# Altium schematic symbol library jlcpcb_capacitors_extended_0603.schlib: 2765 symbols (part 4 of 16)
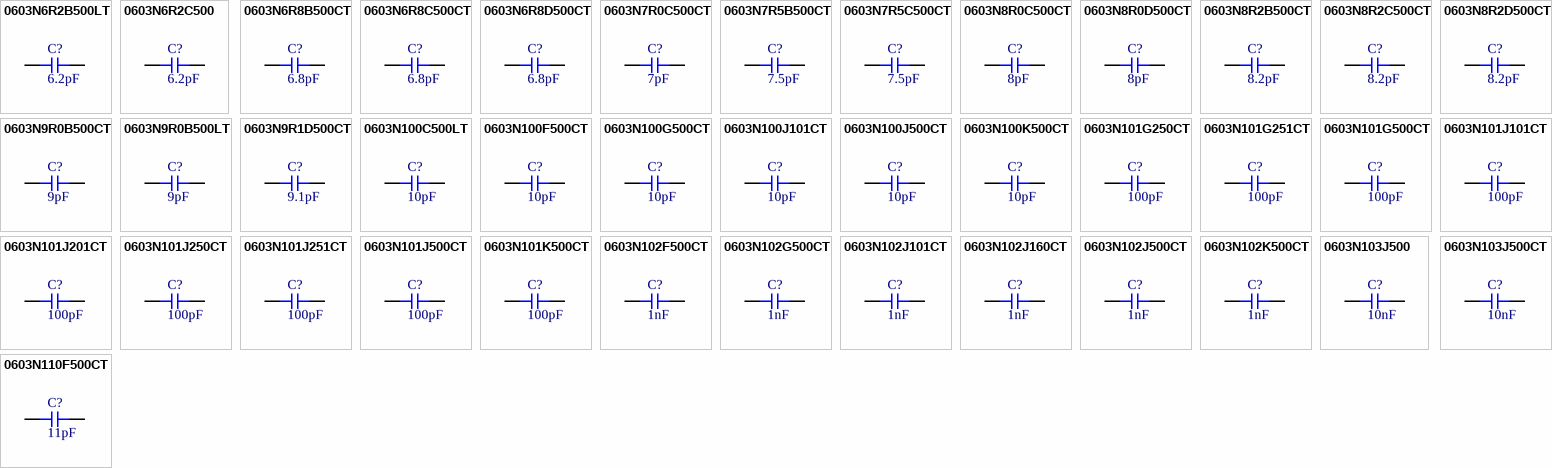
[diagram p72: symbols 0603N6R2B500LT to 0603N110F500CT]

## 0603N9R0B500CT
designator C?  Capacitance: 9pF  (hidden comment: *)
Capacitor, Ceramic (MLCC), 9pF, ±0.1pF, 50V, NP0, ±0.1pF, SMD 0603; Manufacturer: Walsin Tech Corp; Manufacturer Part Number: 0603N9R0B500CT
footprint CAP-0603 (0603 (1608M) Capacitor)
pins: 1, 2

## 0603N9R0B500LT
designator C?  Capacitance: 9pF  (hidden comment: *)
Capacitor, Ceramic (MLCC), 9pF, ±0.1pF, 50V, NP0, ±0.1pF, SMD 0603; Manufacturer: Walsin Tech Corp; Manufacturer Part Number: 0603N9R0B500LT
footprint CAP-0603 (0603 (1608M) Capacitor)
pins: 1, 2

## 0603N9R1D500CT
designator C?  Capacitance: 9.1pF  (hidden comment: *)
Capacitor, Ceramic (MLCC), 9.1pF, ±0.5pF, 50V, NP0, ±0.5pF, SMD 0603; Manufacturer: Walsin Tech Corp; Manufacturer Part Number: 0603N9R1D500CT
footprint CAP-0603 (0603 (1608M) Capacitor)
pins: 1, 2

## 0603N100C500LT
designator C?  Capacitance: 10pF  (hidden comment: *)
Capacitor, Ceramic (MLCC), 10pF, ±0.25pF, 50V, NP0, ±0.25pF, SMD 0603; Manufacturer: Walsin Tech Corp; Manufacturer Part Number: 0603N100C500LT
footprint CAP-0603 (0603 (1608M) Capacitor)
pins: 1, 2

## 0603N100F500CT
designator C?  Capacitance: 10pF  (hidden comment: *)
Capacitor, Ceramic (MLCC), 10pF, ±1%, 50V, NP0, ±1%, SMD 0603; Manufacturer: Walsin Tech Corp; Manufacturer Part Number: 0603N100F500CT
footprint CAP-0603 (0603 (1608M) Capacitor)
pins: 1, 2

## 0603N100G500CT
designator C?  Capacitance: 10pF  (hidden comment: *)
Capacitor, Ceramic (MLCC), 10pF, ±2%, 50V, NP0, ±2%, SMD 0603; Manufacturer: Walsin Tech Corp; Manufacturer Part Number: 0603N100G500CT
footprint CAP-0603 (0603 (1608M) Capacitor)
pins: 1, 2

## 0603N100J101CT
designator C?  Capacitance: 10pF  (hidden comment: *)
Capacitor, Ceramic (MLCC), 10pF, ±5%, 100V, NP0, ±5%, SMD 0603; Manufacturer: Walsin Tech Corp; Manufacturer Part Number: 0603N100J101CT
footprint CAP-0603 (0603 (1608M) Capacitor)
pins: 1, 2

## 0603N100J500CT
designator C?  Capacitance: 10pF  (hidden comment: *)
Capacitor, Ceramic (MLCC), 10pF, ±5%, 50V, NP0, ±5%, SMD 0603; Manufacturer: Walsin Tech Corp; Manufacturer Part Number: 0603N100J500CT
footprint CAP-0603 (0603 (1608M) Capacitor)
pins: 1, 2

## 0603N100K500CT
designator C?  Capacitance: 10pF  (hidden comment: *)
Capacitor, Ceramic (MLCC), 10pF, ±10%, 50V, NP0, ±10%, SMD 0603; Manufacturer: Walsin Tech Corp; Manufacturer Part Number: 0603N100K500CT
footprint CAP-0603 (0603 (1608M) Capacitor)
pins: 1, 2

## 0603N101G250CT
designator C?  Capacitance: 100pF  (hidden comment: *)
Capacitor, Ceramic (MLCC), 100pF, ±2%, 25V, NP0, ±2%, SMD 0603; Manufacturer: Walsin Tech Corp; Manufacturer Part Number: 0603N101G250CT
footprint CAP-0603 (0603 (1608M) Capacitor)
pins: 1, 2

## 0603N101G251CT
designator C?  Capacitance: 100pF  (hidden comment: *)
Capacitor, Ceramic (MLCC), 100pF, ±2%, 250V, NP0, ±2%, SMD 0603; Manufacturer: Walsin Tech Corp; Manufacturer Part Number: 0603N101G251CT
footprint CAP-0603 (0603 (1608M) Capacitor)
pins: 1, 2

## 0603N101G500CT
designator C?  Capacitance: 100pF  (hidden comment: *)
Capacitor, Ceramic (MLCC), 100pF, ±2%, 50V, NP0, ±2%, SMD 0603; Manufacturer: Walsin Tech Corp; Manufacturer Part Number: 0603N101G500CT
footprint CAP-0603 (0603 (1608M) Capacitor)
pins: 1, 2

## 0603N101J101CT
designator C?  Capacitance: 100pF  (hidden comment: *)
Capacitor, Ceramic (MLCC), 100pF, ±5%, 100V, NP0, ±5%, SMD 0603; Manufacturer: Walsin Tech Corp; Manufacturer Part Number: 0603N101J101CT
footprint CAP-0603 (0603 (1608M) Capacitor)
pins: 1, 2

## 0603N101J201CT
designator C?  Capacitance: 100pF  (hidden comment: *)
Capacitor, Ceramic (MLCC), 100pF, ±5%, 200V, NP0, ±5%, SMD 0603; Manufacturer: Walsin Tech Corp; Manufacturer Part Number: 0603N101J201CT
footprint CAP-0603 (0603 (1608M) Capacitor)
pins: 1, 2

## 0603N101J250CT
designator C?  Capacitance: 100pF  (hidden comment: *)
Capacitor, Ceramic (MLCC), 100pF, ±5%, 25V, NP0, ±5%, SMD 0603; Manufacturer: Walsin Tech Corp; Manufacturer Part Number: 0603N101J250CT
footprint CAP-0603 (0603 (1608M) Capacitor)
pins: 1, 2

## 0603N101J251CT
designator C?  Capacitance: 100pF  (hidden comment: *)
Capacitor, Ceramic (MLCC), 100pF, ±5%, 250V, NP0, ±5%, SMD 0603; Manufacturer: Walsin Tech Corp; Manufacturer Part Number: 0603N101J251CT
footprint CAP-0603 (0603 (1608M) Capacitor)
pins: 1, 2

## 0603N101J500CT
designator C?  Capacitance: 100pF  (hidden comment: *)
Capacitor, Ceramic (MLCC), 100pF, ±5%, 50V, NP0, ±5%, SMD 0603; Manufacturer: Walsin Tech Corp; Manufacturer Part Number: 0603N101J500CT
footprint CAP-0603 (0603 (1608M) Capacitor)
pins: 1, 2

## 0603N101K500CT
designator C?  Capacitance: 100pF  (hidden comment: *)
Capacitor, Ceramic (MLCC), 100pF, ±10%, 50V, NP0, ±10%, SMD 0603; Manufacturer: Walsin Tech Corp; Manufacturer Part Number: 0603N101K500CT
footprint CAP-0603 (0603 (1608M) Capacitor)
pins: 1, 2

## 0603N102F500CT
designator C?  Capacitance: 1nF  (hidden comment: *)
Capacitor, Ceramic (MLCC), 1nF, ±1%, 50V, NP0, ±1%, SMD 0603; Manufacturer: Walsin Tech Corp; Manufacturer Part Number: 0603N102F500CT
footprint CAP-0603 (0603 (1608M) Capacitor)
pins: 1, 2

## 0603N102G500CT
designator C?  Capacitance: 1nF  (hidden comment: *)
Capacitor, Ceramic (MLCC), 1nF, ±2%, 50V, NP0, ±2%, SMD 0603; Manufacturer: Walsin Tech Corp; Manufacturer Part Number: 0603N102G500CT
footprint CAP-0603 (0603 (1608M) Capacitor)
pins: 1, 2

## 0603N102J101CT
designator C?  Capacitance: 1nF  (hidden comment: *)
Capacitor, Ceramic (MLCC), 1nF, ±5%, 100V, NP0, ±5%, SMD 0603; Manufacturer: Walsin Tech Corp; Manufacturer Part Number: 0603N102J101CT
footprint CAP-0603 (0603 (1608M) Capacitor)
pins: 1, 2

## 0603N102J160CT
designator C?  Capacitance: 1nF  (hidden comment: *)
Capacitor, Ceramic (MLCC), 1nF, ±5%, 16V, NP0, ±5%, SMD 0603; Manufacturer: Walsin Tech Corp; Manufacturer Part Number: 0603N102J160CT
footprint CAP-0603 (0603 (1608M) Capacitor)
pins: 1, 2

## 0603N102J500CT
designator C?  Capacitance: 1nF  (hidden comment: *)
Capacitor, Ceramic (MLCC), 1nF, ±5%, 50V, NP0, ±5%, SMD 0603; Manufacturer: Walsin Tech Corp; Manufacturer Part Number: 0603N102J500CT
footprint CAP-0603 (0603 (1608M) Capacitor)
pins: 1, 2

## 0603N102K500CT
designator C?  Capacitance: 1nF  (hidden comment: *)
Capacitor, Ceramic (MLCC), 1nF, ±10%, 50V, NP0, ±10%, SMD 0603; Manufacturer: Walsin Tech Corp; Manufacturer Part Number: 0603N102K500CT
footprint CAP-0603 (0603 (1608M) Capacitor)
pins: 1, 2

## 0603N103J500
designator C?  Capacitance: 10nF  (hidden comment: *)
Capacitor, Ceramic (MLCC), 10nF, ±5%, 50V, NP0, ±5%, SMD 0603; Manufacturer: Walsin Tech Corp; Manufacturer Part Number: 0603N103J500
footprint CAP-0603 (0603 (1608M) Capacitor)
pins: 1, 2

## 0603N103J500CT
designator C?  Capacitance: 10nF  (hidden comment: *)
Capacitor, Ceramic (MLCC), 10nF, ±5%, 50V, NP0, ±5%, SMD 0603; Manufacturer: Walsin Tech Corp; Manufacturer Part Number: 0603N103J500CT
footprint CAP-0603 (0603 (1608M) Capacitor)
pins: 1, 2

## 0603N110F500CT
designator C?  Capacitance: 11pF  (hidden comment: *)
Capacitor, Ceramic (MLCC), 11pF, ±1%, 50V, NP0, ±1%, SMD 0603; Manufacturer: Walsin Tech Corp; Manufacturer Part Number: 0603N110F500CT
footprint CAP-0603 (0603 (1608M) Capacitor)
pins: 1, 2

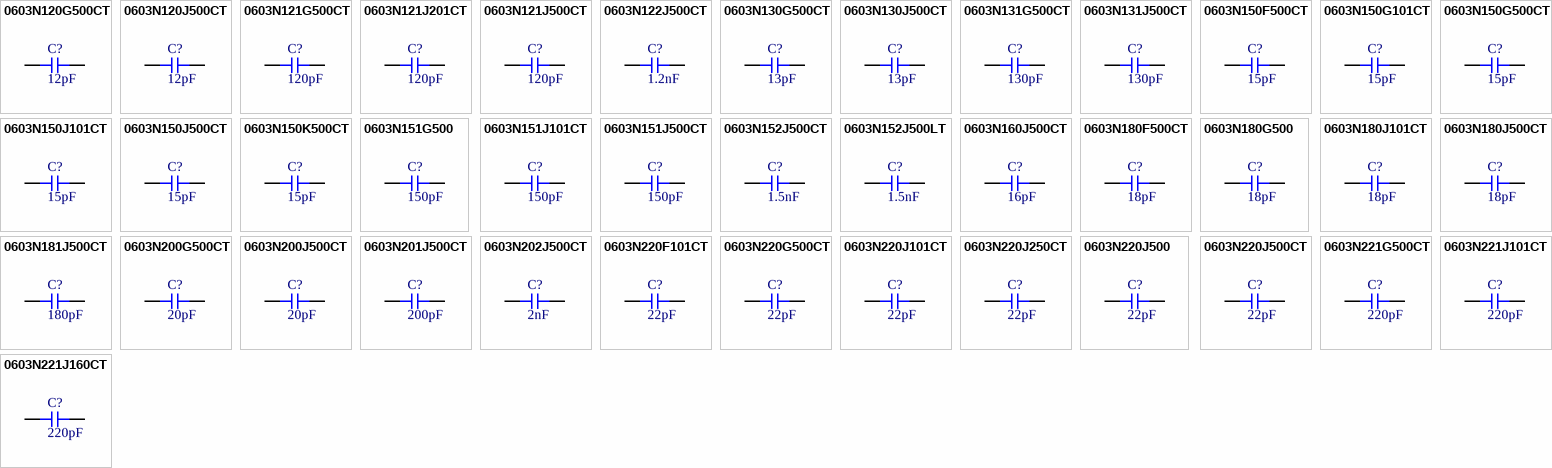
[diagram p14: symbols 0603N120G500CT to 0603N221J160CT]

## 0603N120G500CT
designator C?  Capacitance: 12pF  (hidden comment: *)
Capacitor, Ceramic (MLCC), 12pF, ±2%, 50V, NP0, ±2%, SMD 0603; Manufacturer: Walsin Tech Corp; Manufacturer Part Number: 0603N120G500CT
footprint CAP-0603 (0603 (1608M) Capacitor)
pins: 1, 2

## 0603N120J500CT
designator C?  Capacitance: 12pF  (hidden comment: *)
Capacitor, Ceramic (MLCC), 12pF, ±5%, 50V, NP0, ±5%, SMD 0603; Manufacturer: Walsin Tech Corp; Manufacturer Part Number: 0603N120J500CT
footprint CAP-0603 (0603 (1608M) Capacitor)
pins: 1, 2

## 0603N121G500CT
designator C?  Capacitance: 120pF  (hidden comment: *)
Capacitor, Ceramic (MLCC), 120pF, ±2%, 50V, NP0, ±2%, SMD 0603; Manufacturer: Walsin Tech Corp; Manufacturer Part Number: 0603N121G500CT
footprint CAP-0603 (0603 (1608M) Capacitor)
pins: 1, 2

## 0603N121J201CT
designator C?  Capacitance: 120pF  (hidden comment: *)
Capacitor, Ceramic (MLCC), 120pF, ±5%, 200V, NP0, ±5%, SMD 0603; Manufacturer: Walsin Tech Corp; Manufacturer Part Number: 0603N121J201CT
footprint CAP-0603 (0603 (1608M) Capacitor)
pins: 1, 2

## 0603N121J500CT
designator C?  Capacitance: 120pF  (hidden comment: *)
Capacitor, Ceramic (MLCC), 120pF, ±5%, 50V, NP0, ±5%, SMD 0603; Manufacturer: Walsin Tech Corp; Manufacturer Part Number: 0603N121J500CT
footprint CAP-0603 (0603 (1608M) Capacitor)
pins: 1, 2

## 0603N122J500CT
designator C?  Capacitance: 1.2nF  (hidden comment: *)
Capacitor, Ceramic (MLCC), 1.2nF, ±5%, 50V, NP0, ±5%, SMD 0603; Manufacturer: Walsin Tech Corp; Manufacturer Part Number: 0603N122J500CT
footprint CAP-0603 (0603 (1608M) Capacitor)
pins: 1, 2

## 0603N130G500CT
designator C?  Capacitance: 13pF  (hidden comment: *)
Capacitor, Ceramic (MLCC), 13pF, ±2%, 50V, NP0, ±2%, SMD 0603; Manufacturer: Walsin Tech Corp; Manufacturer Part Number: 0603N130G500CT
footprint CAP-0603 (0603 (1608M) Capacitor)
pins: 1, 2

## 0603N130J500CT
designator C?  Capacitance: 13pF  (hidden comment: *)
Capacitor, Ceramic (MLCC), 13pF, ±5%, 50V, NP0, ±5%, SMD 0603; Manufacturer: Walsin Tech Corp; Manufacturer Part Number: 0603N130J500CT
footprint CAP-0603 (0603 (1608M) Capacitor)
pins: 1, 2

## 0603N131G500CT
designator C?  Capacitance: 130pF  (hidden comment: *)
Capacitor, Ceramic (MLCC), 130pF, ±2%, 50V, NP0, ±2%, SMD 0603; Manufacturer: Walsin Tech Corp; Manufacturer Part Number: 0603N131G500CT
footprint CAP-0603 (0603 (1608M) Capacitor)
pins: 1, 2

## 0603N131J500CT
designator C?  Capacitance: 130pF  (hidden comment: *)
Capacitor, Ceramic (MLCC), 130pF, ±5%, 50V, NP0, ±5%, SMD 0603; Manufacturer: Walsin Tech Corp; Manufacturer Part Number: 0603N131J500CT
footprint CAP-0603 (0603 (1608M) Capacitor)
pins: 1, 2

## 0603N150F500CT
designator C?  Capacitance: 15pF  (hidden comment: *)
Capacitor, Ceramic (MLCC), 15pF, ±1%, 50V, NP0, ±1%, SMD 0603; Manufacturer: Walsin Tech Corp; Manufacturer Part Number: 0603N150F500CT
footprint CAP-0603 (0603 (1608M) Capacitor)
pins: 1, 2

## 0603N150G101CT
designator C?  Capacitance: 15pF  (hidden comment: *)
Capacitor, Ceramic (MLCC), 15pF, ±2%, 100V, NP0, ±2%, SMD 0603; Manufacturer: Walsin Tech Corp; Manufacturer Part Number: 0603N150G101CT
footprint CAP-0603 (0603 (1608M) Capacitor)
pins: 1, 2

## 0603N150G500CT
designator C?  Capacitance: 15pF  (hidden comment: *)
Capacitor, Ceramic (MLCC), 15pF, ±2%, 50V, NP0, ±2%, SMD 0603; Manufacturer: Walsin Tech Corp; Manufacturer Part Number: 0603N150G500CT
footprint CAP-0603 (0603 (1608M) Capacitor)
pins: 1, 2

## 0603N150J101CT
designator C?  Capacitance: 15pF  (hidden comment: *)
Capacitor, Ceramic (MLCC), 15pF, ±5%, 100V, NP0, ±5%, SMD 0603; Manufacturer: Walsin Tech Corp; Manufacturer Part Number: 0603N150J101CT
footprint CAP-0603 (0603 (1608M) Capacitor)
pins: 1, 2

## 0603N150J500CT
designator C?  Capacitance: 15pF  (hidden comment: *)
Capacitor, Ceramic (MLCC), 15pF, ±5%, 50V, NP0, ±5%, SMD 0603; Manufacturer: Walsin Tech Corp; Manufacturer Part Number: 0603N150J500CT
footprint CAP-0603 (0603 (1608M) Capacitor)
pins: 1, 2

## 0603N150K500CT
designator C?  Capacitance: 15pF  (hidden comment: *)
Capacitor, Ceramic (MLCC), 15pF, ±10%, 50V, NP0, ±10%, SMD 0603; Manufacturer: Walsin Tech Corp; Manufacturer Part Number: 0603N150K500CT
footprint CAP-0603 (0603 (1608M) Capacitor)
pins: 1, 2

## 0603N151G500
designator C?  Capacitance: 150pF  (hidden comment: *)
Capacitor, Ceramic (MLCC), 150pF, ±2%, 50V, NP0, ±2%, SMD 0603; Manufacturer: Walsin Tech Corp; Manufacturer Part Number: 0603N151G500
footprint CAP-0603 (0603 (1608M) Capacitor)
pins: 1, 2

## 0603N151J101CT
designator C?  Capacitance: 150pF  (hidden comment: *)
Capacitor, Ceramic (MLCC), 150pF, ±5%, 100V, NP0, ±5%, SMD 0603; Manufacturer: Walsin Tech Corp; Manufacturer Part Number: 0603N151J101CT
footprint CAP-0603 (0603 (1608M) Capacitor)
pins: 1, 2

## 0603N151J500CT
designator C?  Capacitance: 150pF  (hidden comment: *)
Capacitor, Ceramic (MLCC), 150pF, ±5%, 50V, NP0, ±5%, SMD 0603; Manufacturer: Walsin Tech Corp; Manufacturer Part Number: 0603N151J500CT
footprint CAP-0603 (0603 (1608M) Capacitor)
pins: 1, 2

## 0603N152J500CT
designator C?  Capacitance: 1.5nF  (hidden comment: *)
Capacitor, Ceramic (MLCC), 1.5nF, ±5%, 50V, NP0, ±5%, SMD 0603; Manufacturer: Walsin Tech Corp; Manufacturer Part Number: 0603N152J500CT
footprint CAP-0603 (0603 (1608M) Capacitor)
pins: 1, 2

## 0603N152J500LT
designator C?  Capacitance: 1.5nF  (hidden comment: *)
Capacitor, Ceramic (MLCC), 1.5nF, ±5%, 50V, NP0, ±5%, SMD 0603; Manufacturer: Walsin Tech Corp; Manufacturer Part Number: 0603N152J500LT
footprint CAP-0603 (0603 (1608M) Capacitor)
pins: 1, 2

## 0603N160J500CT
designator C?  Capacitance: 16pF  (hidden comment: *)
Capacitor, Ceramic (MLCC), 16pF, ±5%, 50V, NP0, ±5%, SMD 0603; Manufacturer: Walsin Tech Corp; Manufacturer Part Number: 0603N160J500CT
footprint CAP-0603 (0603 (1608M) Capacitor)
pins: 1, 2

## 0603N180F500CT
designator C?  Capacitance: 18pF  (hidden comment: *)
Capacitor, Ceramic (MLCC), 18pF, ±1%, 50V, NP0, ±1%, SMD 0603; Manufacturer: Walsin Tech Corp; Manufacturer Part Number: 0603N180F500CT
footprint CAP-0603 (0603 (1608M) Capacitor)
pins: 1, 2

## 0603N180G500
designator C?  Capacitance: 18pF  (hidden comment: *)
Capacitor, Ceramic (MLCC), 18pF, ±2%, 50V, NP0, ±2%, SMD 0603; Manufacturer: Walsin Tech Corp; Manufacturer Part Number: 0603N180G500
footprint CAP-0603 (0603 (1608M) Capacitor)
pins: 1, 2

## 0603N180J101CT
designator C?  Capacitance: 18pF  (hidden comment: *)
Capacitor, Ceramic (MLCC), 18pF, ±5%, 100V, NP0, ±5%, SMD 0603; Manufacturer: Walsin Tech Corp; Manufacturer Part Number: 0603N180J101CT
footprint CAP-0603 (0603 (1608M) Capacitor)
pins: 1, 2

## 0603N180J500CT
designator C?  Capacitance: 18pF  (hidden comment: *)
Capacitor, Ceramic (MLCC), 18pF, ±5%, 50V, NP0, ±5%, SMD 0603; Manufacturer: Walsin Tech Corp; Manufacturer Part Number: 0603N180J500CT
footprint CAP-0603 (0603 (1608M) Capacitor)
pins: 1, 2

## 0603N181J500CT
designator C?  Capacitance: 180pF  (hidden comment: *)
Capacitor, Ceramic (MLCC), 180pF, ±5%, 50V, NP0, ±5%, SMD 0603; Manufacturer: Walsin Tech Corp; Manufacturer Part Number: 0603N181J500CT
footprint CAP-0603 (0603 (1608M) Capacitor)
pins: 1, 2

## 0603N200G500CT
designator C?  Capacitance: 20pF  (hidden comment: *)
Capacitor, Ceramic (MLCC), 20pF, ±2%, 50V, NP0, ±2%, SMD 0603; Manufacturer: Walsin Tech Corp; Manufacturer Part Number: 0603N200G500CT
footprint CAP-0603 (0603 (1608M) Capacitor)
pins: 1, 2

## 0603N200J500CT
designator C?  Capacitance: 20pF  (hidden comment: *)
Capacitor, Ceramic (MLCC), 20pF, ±5%, 50V, NP0, ±5%, SMD 0603; Manufacturer: Walsin Tech Corp; Manufacturer Part Number: 0603N200J500CT
footprint CAP-0603 (0603 (1608M) Capacitor)
pins: 1, 2

## 0603N201J500CT
designator C?  Capacitance: 200pF  (hidden comment: *)
Capacitor, Ceramic (MLCC), 200pF, ±5%, 50V, NP0, ±5%, SMD 0603; Manufacturer: Walsin Tech Corp; Manufacturer Part Number: 0603N201J500CT
footprint CAP-0603 (0603 (1608M) Capacitor)
pins: 1, 2

## 0603N202J500CT
designator C?  Capacitance: 2nF  (hidden comment: *)
Capacitor, Ceramic (MLCC), 2nF, ±5%, 50V, NP0, ±5%, SMD 0603; Manufacturer: Walsin Tech Corp; Manufacturer Part Number: 0603N202J500CT
footprint CAP-0603 (0603 (1608M) Capacitor)
pins: 1, 2

## 0603N220F101CT
designator C?  Capacitance: 22pF  (hidden comment: *)
Capacitor, Ceramic (MLCC), 22pF, ±1%, 100V, NP0, ±1%, SMD 0603; Manufacturer: Walsin Tech Corp; Manufacturer Part Number: 0603N220F101CT
footprint CAP-0603 (0603 (1608M) Capacitor)
pins: 1, 2

## 0603N220G500CT
designator C?  Capacitance: 22pF  (hidden comment: *)
Capacitor, Ceramic (MLCC), 22pF, ±2%, 50V, NP0, ±2%, SMD 0603; Manufacturer: Walsin Tech Corp; Manufacturer Part Number: 0603N220G500CT
footprint CAP-0603 (0603 (1608M) Capacitor)
pins: 1, 2

## 0603N220J101CT
designator C?  Capacitance: 22pF  (hidden comment: *)
Capacitor, Ceramic (MLCC), 22pF, ±5%, 100V, NP0, ±5%, SMD 0603; Manufacturer: Walsin Tech Corp; Manufacturer Part Number: 0603N220J101CT
footprint CAP-0603 (0603 (1608M) Capacitor)
pins: 1, 2

## 0603N220J250CT
designator C?  Capacitance: 22pF  (hidden comment: *)
Capacitor, Ceramic (MLCC), 22pF, ±5%, 25V, NP0, ±5%, SMD 0603; Manufacturer: Walsin Tech Corp; Manufacturer Part Number: 0603N220J250CT
footprint CAP-0603 (0603 (1608M) Capacitor)
pins: 1, 2

## 0603N220J500
designator C?  Capacitance: 22pF  (hidden comment: *)
Capacitor, Ceramic (MLCC), 22pF, ±5%, 50V, NP0, ±5%, SMD 0603; Manufacturer: Walsin Tech Corp; Manufacturer Part Number: 0603N220J500
footprint CAP-0603 (0603 (1608M) Capacitor)
pins: 1, 2

## 0603N220J500CT
designator C?  Capacitance: 22pF  (hidden comment: *)
Capacitor, Ceramic (MLCC), 22pF, ±5%, 50V, NP0, ±5%, SMD 0603; Manufacturer: Walsin Tech Corp; Manufacturer Part Number: 0603N220J500CT
footprint CAP-0603 (0603 (1608M) Capacitor)
pins: 1, 2

## 0603N221G500CT
designator C?  Capacitance: 220pF  (hidden comment: *)
Capacitor, Ceramic (MLCC), 220pF, ±2%, 50V, NP0, ±2%, SMD 0603; Manufacturer: Walsin Tech Corp; Manufacturer Part Number: 0603N221G500CT
footprint CAP-0603 (0603 (1608M) Capacitor)
pins: 1, 2

## 0603N221J101CT
designator C?  Capacitance: 220pF  (hidden comment: *)
Capacitor, Ceramic (MLCC), 220pF, ±5%, 100V, NP0, ±5%, SMD 0603; Manufacturer: Walsin Tech Corp; Manufacturer Part Number: 0603N221J101CT
footprint CAP-0603 (0603 (1608M) Capacitor)
pins: 1, 2

## 0603N221J160CT
designator C?  Capacitance: 220pF  (hidden comment: *)
Capacitor, Ceramic (MLCC), 220pF, ±5%, 16V, NP0, ±5%, SMD 0603; Manufacturer: Walsin Tech Corp; Manufacturer Part Number: 0603N221J160CT
footprint CAP-0603 (0603 (1608M) Capacitor)
pins: 1, 2

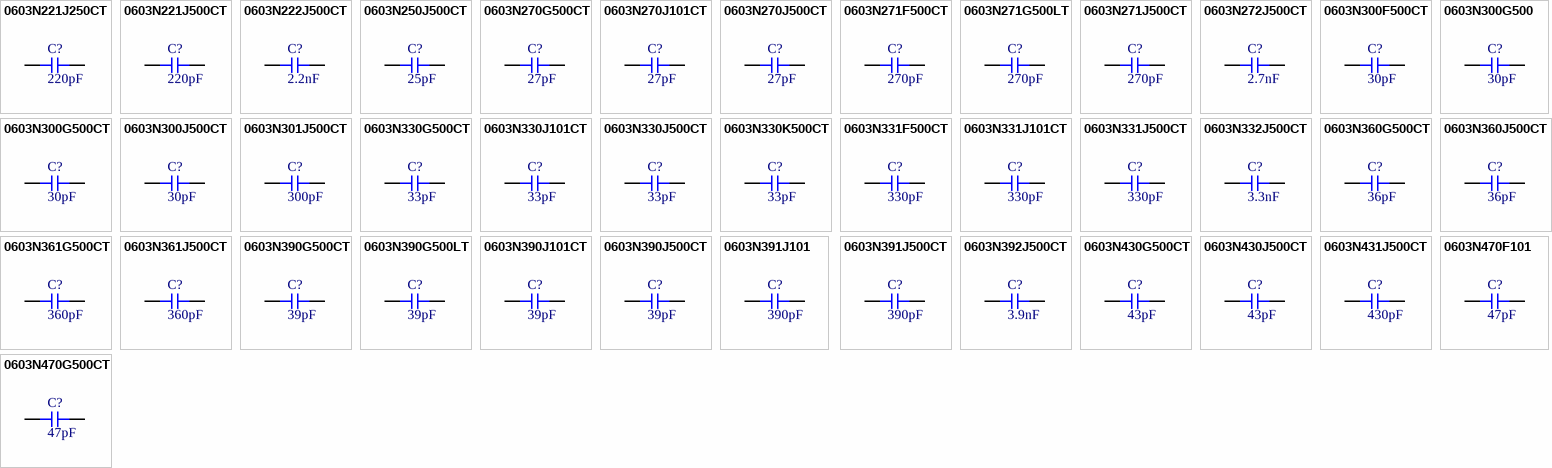
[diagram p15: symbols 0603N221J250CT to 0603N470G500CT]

## 0603N221J250CT
designator C?  Capacitance: 220pF  (hidden comment: *)
Capacitor, Ceramic (MLCC), 220pF, ±5%, 25V, NP0, ±5%, SMD 0603; Manufacturer: Walsin Tech Corp; Manufacturer Part Number: 0603N221J250CT
footprint CAP-0603 (0603 (1608M) Capacitor)
pins: 1, 2

## 0603N221J500CT
designator C?  Capacitance: 220pF  (hidden comment: *)
Capacitor, Ceramic (MLCC), 220pF, ±5%, 50V, NP0, ±5%, SMD 0603; Manufacturer: Walsin Tech Corp; Manufacturer Part Number: 0603N221J500CT
footprint CAP-0603 (0603 (1608M) Capacitor)
pins: 1, 2

## 0603N222J500CT
designator C?  Capacitance: 2.2nF  (hidden comment: *)
Capacitor, Ceramic (MLCC), 2.2nF, ±5%, 50V, NP0, ±5%, SMD 0603; Manufacturer: Walsin Tech Corp; Manufacturer Part Number: 0603N222J500CT
footprint CAP-0603 (0603 (1608M) Capacitor)
pins: 1, 2

## 0603N250J500CT
designator C?  Capacitance: 25pF  (hidden comment: *)
Capacitor, Ceramic (MLCC), 25pF, ±5%, 50V, NP0, ±5%, SMD 0603; Manufacturer: Walsin Tech Corp; Manufacturer Part Number: 0603N250J500CT
footprint CAP-0603 (0603 (1608M) Capacitor)
pins: 1, 2

## 0603N270G500CT
designator C?  Capacitance: 27pF  (hidden comment: *)
Capacitor, Ceramic (MLCC), 27pF, ±2%, 50V, NP0, ±2%, SMD 0603; Manufacturer: Walsin Tech Corp; Manufacturer Part Number: 0603N270G500CT
footprint CAP-0603 (0603 (1608M) Capacitor)
pins: 1, 2

## 0603N270J101CT
designator C?  Capacitance: 27pF  (hidden comment: *)
Capacitor, Ceramic (MLCC), 27pF, ±5%, 100V, NP0, ±5%, SMD 0603; Manufacturer: Walsin Tech Corp; Manufacturer Part Number: 0603N270J101CT
footprint CAP-0603 (0603 (1608M) Capacitor)
pins: 1, 2

## 0603N270J500CT
designator C?  Capacitance: 27pF  (hidden comment: *)
Capacitor, Ceramic (MLCC), 27pF, ±5%, 50V, NP0, ±5%, SMD 0603; Manufacturer: Walsin Tech Corp; Manufacturer Part Number: 0603N270J500CT
footprint CAP-0603 (0603 (1608M) Capacitor)
pins: 1, 2

## 0603N271F500CT
designator C?  Capacitance: 270pF  (hidden comment: *)
Capacitor, Ceramic (MLCC), 270pF, ±1%, 50V, NP0, ±1%, SMD 0603; Manufacturer: Walsin Tech Corp; Manufacturer Part Number: 0603N271F500CT
footprint CAP-0603 (0603 (1608M) Capacitor)
pins: 1, 2

## 0603N271G500LT
designator C?  Capacitance: 270pF  (hidden comment: *)
Capacitor, Ceramic (MLCC), 270pF, ±2%, 50V, NP0, ±2%, SMD 0603; Manufacturer: Walsin Tech Corp; Manufacturer Part Number: 0603N271G500LT
footprint CAP-0603 (0603 (1608M) Capacitor)
pins: 1, 2

## 0603N271J500CT
designator C?  Capacitance: 270pF  (hidden comment: *)
Capacitor, Ceramic (MLCC), 270pF, ±5%, 50V, NP0, ±5%, SMD 0603; Manufacturer: Walsin Tech Corp; Manufacturer Part Number: 0603N271J500CT
footprint CAP-0603 (0603 (1608M) Capacitor)
pins: 1, 2

## 0603N272J500CT
designator C?  Capacitance: 2.7nF  (hidden comment: *)
Capacitor, Ceramic (MLCC), 2.7nF, ±5%, 50V, NP0, ±5%, SMD 0603; Manufacturer: Walsin Tech Corp; Manufacturer Part Number: 0603N272J500CT
footprint CAP-0603 (0603 (1608M) Capacitor)
pins: 1, 2

## 0603N300F500CT
designator C?  Capacitance: 30pF  (hidden comment: *)
Capacitor, Ceramic (MLCC), 30pF, ±1%, 50V, NP0, ±1%, SMD 0603; Manufacturer: Walsin Tech Corp; Manufacturer Part Number: 0603N300F500CT
footprint CAP-0603 (0603 (1608M) Capacitor)
pins: 1, 2

## 0603N300G500
designator C?  Capacitance: 30pF  (hidden comment: *)
Capacitor, Ceramic (MLCC), 30pF, ±2%, 50V, NP0, ±2%, SMD 0603; Manufacturer: Walsin Tech Corp; Manufacturer Part Number: 0603N300G500
footprint CAP-0603 (0603 (1608M) Capacitor)
pins: 1, 2

## 0603N300G500CT
designator C?  Capacitance: 30pF  (hidden comment: *)
Capacitor, Ceramic (MLCC), 30pF, ±2%, 50V, NP0, ±2%, SMD 0603; Manufacturer: Walsin Tech Corp; Manufacturer Part Number: 0603N300G500CT
footprint CAP-0603 (0603 (1608M) Capacitor)
pins: 1, 2

## 0603N300J500CT
designator C?  Capacitance: 30pF  (hidden comment: *)
Capacitor, Ceramic (MLCC), 30pF, ±5%, 50V, NP0, ±5%, SMD 0603; Manufacturer: Walsin Tech Corp; Manufacturer Part Number: 0603N300J500CT
footprint CAP-0603 (0603 (1608M) Capacitor)
pins: 1, 2

## 0603N301J500CT
designator C?  Capacitance: 300pF  (hidden comment: *)
Capacitor, Ceramic (MLCC), 300pF, ±5%, 50V, NP0, ±5%, SMD 0603; Manufacturer: Walsin Tech Corp; Manufacturer Part Number: 0603N301J500CT
footprint CAP-0603 (0603 (1608M) Capacitor)
pins: 1, 2

## 0603N330G500CT
designator C?  Capacitance: 33pF  (hidden comment: *)
Capacitor, Ceramic (MLCC), 33pF, ±2%, 50V, NP0, ±2%, SMD 0603; Manufacturer: Walsin Tech Corp; Manufacturer Part Number: 0603N330G500CT
footprint CAP-0603 (0603 (1608M) Capacitor)
pins: 1, 2

## 0603N330J101CT
designator C?  Capacitance: 33pF  (hidden comment: *)
Capacitor, Ceramic (MLCC), 33pF, ±5%, 100V, NP0, ±5%, SMD 0603; Manufacturer: Walsin Tech Corp; Manufacturer Part Number: 0603N330J101CT
footprint CAP-0603 (0603 (1608M) Capacitor)
pins: 1, 2

## 0603N330J500CT
designator C?  Capacitance: 33pF  (hidden comment: *)
Capacitor, Ceramic (MLCC), 33pF, ±5%, 50V, NP0, ±5%, SMD 0603; Manufacturer: Walsin Tech Corp; Manufacturer Part Number: 0603N330J500CT
footprint CAP-0603 (0603 (1608M) Capacitor)
pins: 1, 2

## 0603N330K500CT
designator C?  Capacitance: 33pF  (hidden comment: *)
Capacitor, Ceramic (MLCC), 33pF, ±10%, 50V, NP0, ±10%, SMD 0603; Manufacturer: Walsin Tech Corp; Manufacturer Part Number: 0603N330K500CT
footprint CAP-0603 (0603 (1608M) Capacitor)
pins: 1, 2

## 0603N331F500CT
designator C?  Capacitance: 330pF  (hidden comment: *)
Capacitor, Ceramic (MLCC), 330pF, ±1%, 50V, NP0, ±1%, SMD 0603; Manufacturer: Walsin Tech Corp; Manufacturer Part Number: 0603N331F500CT
footprint CAP-0603 (0603 (1608M) Capacitor)
pins: 1, 2

## 0603N331J101CT
designator C?  Capacitance: 330pF  (hidden comment: *)
Capacitor, Ceramic (MLCC), 330pF, ±5%, 100V, NP0, ±5%, SMD 0603; Manufacturer: Walsin Tech Corp; Manufacturer Part Number: 0603N331J101CT
footprint CAP-0603 (0603 (1608M) Capacitor)
pins: 1, 2

## 0603N331J500CT
designator C?  Capacitance: 330pF  (hidden comment: *)
Capacitor, Ceramic (MLCC), 330pF, ±5%, 50V, NP0, ±5%, SMD 0603; Manufacturer: Walsin Tech Corp; Manufacturer Part Number: 0603N331J500CT
footprint CAP-0603 (0603 (1608M) Capacitor)
pins: 1, 2

## 0603N332J500CT
designator C?  Capacitance: 3.3nF  (hidden comment: *)
Capacitor, Ceramic (MLCC), 3.3nF, ±5%, 50V, NP0, ±5%, SMD 0603; Manufacturer: Walsin Tech Corp; Manufacturer Part Number: 0603N332J500CT
footprint CAP-0603 (0603 (1608M) Capacitor)
pins: 1, 2

## 0603N360G500CT
designator C?  Capacitance: 36pF  (hidden comment: *)
Capacitor, Ceramic (MLCC), 36pF, ±2%, 50V, NP0, ±2%, SMD 0603; Manufacturer: Walsin Tech Corp; Manufacturer Part Number: 0603N360G500CT
footprint CAP-0603 (0603 (1608M) Capacitor)
pins: 1, 2

## 0603N360J500CT
designator C?  Capacitance: 36pF  (hidden comment: *)
Capacitor, Ceramic (MLCC), 36pF, ±5%, 50V, NP0, ±5%, SMD 0603; Manufacturer: Walsin Tech Corp; Manufacturer Part Number: 0603N360J500CT
footprint CAP-0603 (0603 (1608M) Capacitor)
pins: 1, 2

## 0603N361G500CT
designator C?  Capacitance: 360pF  (hidden comment: *)
Capacitor, Ceramic (MLCC), 360pF, ±2%, 50V, NP0, ±2%, SMD 0603; Manufacturer: Walsin Tech Corp; Manufacturer Part Number: 0603N361G500CT
footprint CAP-0603 (0603 (1608M) Capacitor)
pins: 1, 2

## 0603N361J500CT
designator C?  Capacitance: 360pF  (hidden comment: *)
Capacitor, Ceramic (MLCC), 360pF, ±5%, 50V, NP0, ±5%, SMD 0603; Manufacturer: Walsin Tech Corp; Manufacturer Part Number: 0603N361J500CT
footprint CAP-0603 (0603 (1608M) Capacitor)
pins: 1, 2

## 0603N390G500CT
designator C?  Capacitance: 39pF  (hidden comment: *)
Capacitor, Ceramic (MLCC), 39pF, ±2%, 50V, NP0, ±2%, SMD 0603; Manufacturer: Walsin Tech Corp; Manufacturer Part Number: 0603N390G500CT
footprint CAP-0603 (0603 (1608M) Capacitor)
pins: 1, 2

## 0603N390G500LT
designator C?  Capacitance: 39pF  (hidden comment: *)
Capacitor, Ceramic (MLCC), 39pF, ±2%, 50V, NP0, ±2%, SMD 0603; Manufacturer: Walsin Tech Corp; Manufacturer Part Number: 0603N390G500LT
footprint CAP-0603 (0603 (1608M) Capacitor)
pins: 1, 2

## 0603N390J101CT
designator C?  Capacitance: 39pF  (hidden comment: *)
Capacitor, Ceramic (MLCC), 39pF, ±5%, 100V, NP0, ±5%, SMD 0603; Manufacturer: Walsin Tech Corp; Manufacturer Part Number: 0603N390J101CT
footprint CAP-0603 (0603 (1608M) Capacitor)
pins: 1, 2

## 0603N390J500CT
designator C?  Capacitance: 39pF  (hidden comment: *)
Capacitor, Ceramic (MLCC), 39pF, ±5%, 50V, NP0, ±5%, SMD 0603; Manufacturer: Walsin Tech Corp; Manufacturer Part Number: 0603N390J500CT
footprint CAP-0603 (0603 (1608M) Capacitor)
pins: 1, 2

## 0603N391J101
designator C?  Capacitance: 390pF  (hidden comment: *)
Capacitor, Ceramic (MLCC), 390pF, ±5%, 100V, NP0, ±5%, SMD 0603; Manufacturer: Walsin Tech Corp; Manufacturer Part Number: 0603N391J101
footprint CAP-0603 (0603 (1608M) Capacitor)
pins: 1, 2

## 0603N391J500CT
designator C?  Capacitance: 390pF  (hidden comment: *)
Capacitor, Ceramic (MLCC), 390pF, ±5%, 50V, NP0, ±5%, SMD 0603; Manufacturer: Walsin Tech Corp; Manufacturer Part Number: 0603N391J500CT
footprint CAP-0603 (0603 (1608M) Capacitor)
pins: 1, 2

## 0603N392J500CT
designator C?  Capacitance: 3.9nF  (hidden comment: *)
Capacitor, Ceramic (MLCC), 3.9nF, ±5%, 50V, NP0, ±5%, SMD 0603; Manufacturer: Walsin Tech Corp; Manufacturer Part Number: 0603N392J500CT
footprint CAP-0603 (0603 (1608M) Capacitor)
pins: 1, 2

## 0603N430G500CT
designator C?  Capacitance: 43pF  (hidden comment: *)
Capacitor, Ceramic (MLCC), 43pF, ±2%, 50V, NP0, ±2%, SMD 0603; Manufacturer: Walsin Tech Corp; Manufacturer Part Number: 0603N430G500CT
footprint CAP-0603 (0603 (1608M) Capacitor)
pins: 1, 2

## 0603N430J500CT
designator C?  Capacitance: 43pF  (hidden comment: *)
Capacitor, Ceramic (MLCC), 43pF, ±5%, 50V, NP0, ±5%, SMD 0603; Manufacturer: Walsin Tech Corp; Manufacturer Part Number: 0603N430J500CT
footprint CAP-0603 (0603 (1608M) Capacitor)
pins: 1, 2

## 0603N431J500CT
designator C?  Capacitance: 430pF  (hidden comment: *)
Capacitor, Ceramic (MLCC), 430pF, ±5%, 50V, NP0, ±5%, SMD 0603; Manufacturer: Walsin Tech Corp; Manufacturer Part Number: 0603N431J500CT
footprint CAP-0603 (0603 (1608M) Capacitor)
pins: 1, 2

## 0603N470F101
designator C?  Capacitance: 47pF  (hidden comment: *)
Capacitor, Ceramic (MLCC), 47pF, ±1%, 100V, NP0, ±1%, SMD 0603; Manufacturer: Walsin Tech Corp; Manufacturer Part Number: 0603N470F101
footprint CAP-0603 (0603 (1608M) Capacitor)
pins: 1, 2

## 0603N470G500CT
designator C?  Capacitance: 47pF  (hidden comment: *)
Capacitor, Ceramic (MLCC), 47pF, ±2%, 50V, NP0, ±2%, SMD 0603; Manufacturer: Walsin Tech Corp; Manufacturer Part Number: 0603N470G500CT
footprint CAP-0603 (0603 (1608M) Capacitor)
pins: 1, 2

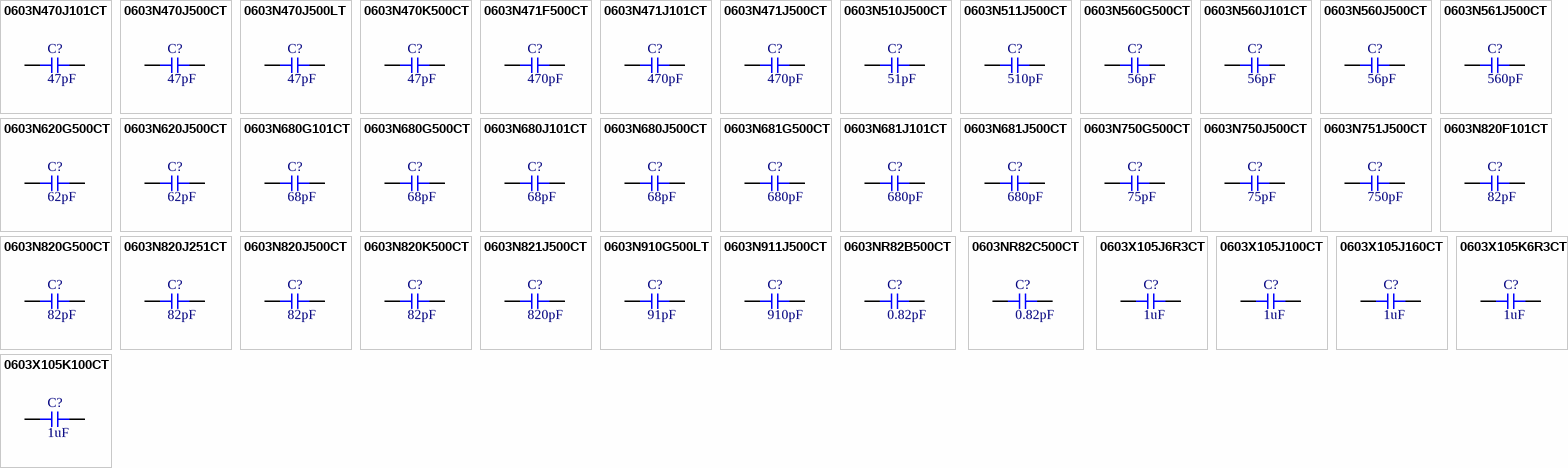
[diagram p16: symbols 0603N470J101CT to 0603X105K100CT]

## 0603N470J101CT
designator C?  Capacitance: 47pF  (hidden comment: *)
Capacitor, Ceramic (MLCC), 47pF, ±5%, 100V, NP0, ±5%, SMD 0603; Manufacturer: Walsin Tech Corp; Manufacturer Part Number: 0603N470J101CT
footprint CAP-0603 (0603 (1608M) Capacitor)
pins: 1, 2

## 0603N470J500CT
designator C?  Capacitance: 47pF  (hidden comment: *)
Capacitor, Ceramic (MLCC), 47pF, ±5%, 50V, NP0, ±5%, SMD 0603; Manufacturer: Walsin Tech Corp; Manufacturer Part Number: 0603N470J500CT
footprint CAP-0603 (0603 (1608M) Capacitor)
pins: 1, 2

## 0603N470J500LT
designator C?  Capacitance: 47pF  (hidden comment: *)
Capacitor, Ceramic (MLCC), 47pF, ±5%, 50V, NP0, ±5%, SMD 0603; Manufacturer: Walsin Tech Corp; Manufacturer Part Number: 0603N470J500LT
footprint CAP-0603 (0603 (1608M) Capacitor)
pins: 1, 2

## 0603N470K500CT
designator C?  Capacitance: 47pF  (hidden comment: *)
Capacitor, Ceramic (MLCC), 47pF, ±10%, 50V, NP0, ±10%, SMD 0603; Manufacturer: Walsin Tech Corp; Manufacturer Part Number: 0603N470K500CT
footprint CAP-0603 (0603 (1608M) Capacitor)
pins: 1, 2

## 0603N471F500CT
designator C?  Capacitance: 470pF  (hidden comment: *)
Capacitor, Ceramic (MLCC), 470pF, ±1%, 50V, NP0, ±1%, SMD 0603; Manufacturer: Walsin Tech Corp; Manufacturer Part Number: 0603N471F500CT
footprint CAP-0603 (0603 (1608M) Capacitor)
pins: 1, 2

## 0603N471J101CT
designator C?  Capacitance: 470pF  (hidden comment: *)
Capacitor, Ceramic (MLCC), 470pF, ±5%, 100V, NP0, ±5%, SMD 0603; Manufacturer: Walsin Tech Corp; Manufacturer Part Number: 0603N471J101CT
footprint CAP-0603 (0603 (1608M) Capacitor)
pins: 1, 2

## 0603N471J500CT
designator C?  Capacitance: 470pF  (hidden comment: *)
Capacitor, Ceramic (MLCC), 470pF, ±5%, 50V, NP0, ±5%, SMD 0603; Manufacturer: Walsin Tech Corp; Manufacturer Part Number: 0603N471J500CT
footprint CAP-0603 (0603 (1608M) Capacitor)
pins: 1, 2

## 0603N510J500CT
designator C?  Capacitance: 51pF  (hidden comment: *)
Capacitor, Ceramic (MLCC), 51pF, ±5%, 50V, NP0, ±5%, SMD 0603; Manufacturer: Walsin Tech Corp; Manufacturer Part Number: 0603N510J500CT
footprint CAP-0603 (0603 (1608M) Capacitor)
pins: 1, 2

## 0603N511J500CT
designator C?  Capacitance: 510pF  (hidden comment: *)
Capacitor, Ceramic (MLCC), 510pF, ±5%, 50V, NP0, ±5%, SMD 0603; Manufacturer: Walsin Tech Corp; Manufacturer Part Number: 0603N511J500CT
footprint CAP-0603 (0603 (1608M) Capacitor)
pins: 1, 2

## 0603N560G500CT
designator C?  Capacitance: 56pF  (hidden comment: *)
Capacitor, Ceramic (MLCC), 56pF, ±2%, 50V, NP0, ±2%, SMD 0603; Manufacturer: Walsin Tech Corp; Manufacturer Part Number: 0603N560G500CT
footprint CAP-0603 (0603 (1608M) Capacitor)
pins: 1, 2

## 0603N560J101CT
designator C?  Capacitance: 56pF  (hidden comment: *)
Capacitor, Ceramic (MLCC), 56pF, ±5%, 100V, NP0, ±5%, SMD 0603; Manufacturer: Walsin Tech Corp; Manufacturer Part Number: 0603N560J101CT
footprint CAP-0603 (0603 (1608M) Capacitor)
pins: 1, 2

## 0603N560J500CT
designator C?  Capacitance: 56pF  (hidden comment: *)
Capacitor, Ceramic (MLCC), 56pF, ±5%, 50V, NP0, ±5%, SMD 0603; Manufacturer: Walsin Tech Corp; Manufacturer Part Number: 0603N560J500CT
footprint CAP-0603 (0603 (1608M) Capacitor)
pins: 1, 2

## 0603N561J500CT
designator C?  Capacitance: 560pF  (hidden comment: *)
Capacitor, Ceramic (MLCC), 560pF, ±5%, 50V, NP0, ±5%, SMD 0603; Manufacturer: Walsin Tech Corp; Manufacturer Part Number: 0603N561J500CT
footprint CAP-0603 (0603 (1608M) Capacitor)
pins: 1, 2

## 0603N620G500CT
designator C?  Capacitance: 62pF  (hidden comment: *)
Capacitor, Ceramic (MLCC), 62pF, ±2%, 50V, NP0, ±2%, SMD 0603; Manufacturer: Walsin Tech Corp; Manufacturer Part Number: 0603N620G500CT
footprint CAP-0603 (0603 (1608M) Capacitor)
pins: 1, 2

## 0603N620J500CT
designator C?  Capacitance: 62pF  (hidden comment: *)
Capacitor, Ceramic (MLCC), 62pF, ±5%, 50V, NP0, ±5%, SMD 0603; Manufacturer: Walsin Tech Corp; Manufacturer Part Number: 0603N620J500CT
footprint CAP-0603 (0603 (1608M) Capacitor)
pins: 1, 2

## 0603N680G101CT
designator C?  Capacitance: 68pF  (hidden comment: *)
Capacitor, Ceramic (MLCC), 68pF, ±2%, 100V, NP0, ±2%, SMD 0603; Manufacturer: Walsin Tech Corp; Manufacturer Part Number: 0603N680G101CT
footprint CAP-0603 (0603 (1608M) Capacitor)
pins: 1, 2

## 0603N680G500CT
designator C?  Capacitance: 68pF  (hidden comment: *)
Capacitor, Ceramic (MLCC), 68pF, ±2%, 50V, NP0, ±2%, SMD 0603; Manufacturer: Walsin Tech Corp; Manufacturer Part Number: 0603N680G500CT
footprint CAP-0603 (0603 (1608M) Capacitor)
pins: 1, 2

## 0603N680J101CT
designator C?  Capacitance: 68pF  (hidden comment: *)
Capacitor, Ceramic (MLCC), 68pF, ±5%, 100V, NP0, ±5%, SMD 0603; Manufacturer: Walsin Tech Corp; Manufacturer Part Number: 0603N680J101CT
footprint CAP-0603 (0603 (1608M) Capacitor)
pins: 1, 2

## 0603N680J500CT
designator C?  Capacitance: 68pF  (hidden comment: *)
Capacitor, Ceramic (MLCC), 68pF, ±5%, 50V, NP0, ±5%, SMD 0603; Manufacturer: Walsin Tech Corp; Manufacturer Part Number: 0603N680J500CT
footprint CAP-0603 (0603 (1608M) Capacitor)
pins: 1, 2

## 0603N681G500CT
designator C?  Capacitance: 680pF  (hidden comment: *)
Capacitor, Ceramic (MLCC), 680pF, ±2%, 50V, NP0, ±2%, SMD 0603; Manufacturer: Walsin Tech Corp; Manufacturer Part Number: 0603N681G500CT
footprint CAP-0603 (0603 (1608M) Capacitor)
pins: 1, 2

## 0603N681J101CT
designator C?  Capacitance: 680pF  (hidden comment: *)
Capacitor, Ceramic (MLCC), 680pF, ±5%, 100V, NP0, ±5%, SMD 0603; Manufacturer: Walsin Tech Corp; Manufacturer Part Number: 0603N681J101CT
footprint CAP-0603 (0603 (1608M) Capacitor)
pins: 1, 2

## 0603N681J500CT
designator C?  Capacitance: 680pF  (hidden comment: *)
Capacitor, Ceramic (MLCC), 680pF, ±5%, 50V, NP0, ±5%, SMD 0603; Manufacturer: Walsin Tech Corp; Manufacturer Part Number: 0603N681J500CT
footprint CAP-0603 (0603 (1608M) Capacitor)
pins: 1, 2

## 0603N750G500CT
designator C?  Capacitance: 75pF  (hidden comment: *)
Capacitor, Ceramic (MLCC), 75pF, ±2%, 50V, NP0, ±2%, SMD 0603; Manufacturer: Walsin Tech Corp; Manufacturer Part Number: 0603N750G500CT
footprint CAP-0603 (0603 (1608M) Capacitor)
pins: 1, 2

## 0603N750J500CT
designator C?  Capacitance: 75pF  (hidden comment: *)
Capacitor, Ceramic (MLCC), 75pF, ±5%, 50V, NP0, ±5%, SMD 0603; Manufacturer: Walsin Tech Corp; Manufacturer Part Number: 0603N750J500CT
footprint CAP-0603 (0603 (1608M) Capacitor)
pins: 1, 2

## 0603N751J500CT
designator C?  Capacitance: 750pF  (hidden comment: *)
Capacitor, Ceramic (MLCC), 750pF, ±5%, 50V, NP0, ±5%, SMD 0603; Manufacturer: Walsin Tech Corp; Manufacturer Part Number: 0603N751J500CT
footprint CAP-0603 (0603 (1608M) Capacitor)
pins: 1, 2

## 0603N820F101CT
designator C?  Capacitance: 82pF  (hidden comment: *)
Capacitor, Ceramic (MLCC), 82pF, ±1%, 100V, NP0, ±1%, SMD 0603; Manufacturer: Walsin Tech Corp; Manufacturer Part Number: 0603N820F101CT
footprint CAP-0603 (0603 (1608M) Capacitor)
pins: 1, 2

## 0603N820G500CT
designator C?  Capacitance: 82pF  (hidden comment: *)
Capacitor, Ceramic (MLCC), 82pF, ±2%, 50V, NP0, ±2%, SMD 0603; Manufacturer: Walsin Tech Corp; Manufacturer Part Number: 0603N820G500CT
footprint CAP-0603 (0603 (1608M) Capacitor)
pins: 1, 2

## 0603N820J251CT
designator C?  Capacitance: 82pF  (hidden comment: *)
Capacitor, Ceramic (MLCC), 82pF, ±5%, 250V, NP0, ±5%, SMD 0603; Manufacturer: Walsin Tech Corp; Manufacturer Part Number: 0603N820J251CT
footprint CAP-0603 (0603 (1608M) Capacitor)
pins: 1, 2

## 0603N820J500CT
designator C?  Capacitance: 82pF  (hidden comment: *)
Capacitor, Ceramic (MLCC), 82pF, ±5%, 50V, NP0, ±5%, SMD 0603; Manufacturer: Walsin Tech Corp; Manufacturer Part Number: 0603N820J500CT
footprint CAP-0603 (0603 (1608M) Capacitor)
pins: 1, 2

## 0603N820K500CT
designator C?  Capacitance: 82pF  (hidden comment: *)
Capacitor, Ceramic (MLCC), 82pF, ±10%, 50V, NP0, ±10%, SMD 0603; Manufacturer: Walsin Tech Corp; Manufacturer Part Number: 0603N820K500CT
footprint CAP-0603 (0603 (1608M) Capacitor)
pins: 1, 2

## 0603N821J500CT
designator C?  Capacitance: 820pF  (hidden comment: *)
Capacitor, Ceramic (MLCC), 820pF, ±5%, 50V, NP0, ±5%, SMD 0603; Manufacturer: Walsin Tech Corp; Manufacturer Part Number: 0603N821J500CT
footprint CAP-0603 (0603 (1608M) Capacitor)
pins: 1, 2

## 0603N910G500LT
designator C?  Capacitance: 91pF  (hidden comment: *)
Capacitor, Ceramic (MLCC), 91pF, ±2%, 50V, NP0, ±2%, SMD 0603; Manufacturer: Walsin Tech Corp; Manufacturer Part Number: 0603N910G500LT
footprint CAP-0603 (0603 (1608M) Capacitor)
pins: 1, 2

## 0603N911J500CT
designator C?  Capacitance: 910pF  (hidden comment: *)
Capacitor, Ceramic (MLCC), 910pF, ±5%, 50V, NP0, ±5%, SMD 0603; Manufacturer: Walsin Tech Corp; Manufacturer Part Number: 0603N911J500CT
footprint CAP-0603 (0603 (1608M) Capacitor)
pins: 1, 2

## 0603NR82B500CT
designator C?  Capacitance: 0.82pF  (hidden comment: *)
Capacitor, Ceramic (MLCC), 0.82pF, ±0.1pF, 50V, NP0, ±0.1pF, SMD 0603; Manufacturer: Walsin Tech Corp; Manufacturer Part Number: 0603NR82B500CT
footprint CAP-0603 (0603 (1608M) Capacitor)
pins: 1, 2

## 0603NR82C500CT
designator C?  Capacitance: 0.82pF  (hidden comment: *)
Capacitor, Ceramic (MLCC), 0.82pF, ±0.25pF, 50V, NP0, ±0.25pF, SMD 0603; Manufacturer: Walsin Tech Corp; Manufacturer Part Number: 0603NR82C500CT
footprint CAP-0603 (0603 (1608M) Capacitor)
pins: 1, 2

## 0603X105J6R3CT
designator C?  Capacitance: 1uF  (hidden comment: *)
Capacitor, Ceramic (MLCC), 1uF, ±5%, 6.3V, X5R, ±5%, SMD 0603; Manufacturer: Walsin Tech Corp; Manufacturer Part Number: 0603X105J6R3CT
footprint CAP-0603 (0603 (1608M) Capacitor)
pins: 1, 2

## 0603X105J100CT
designator C?  Capacitance: 1uF  (hidden comment: *)
Capacitor, Ceramic (MLCC), 1uF, ±5%, 10V, X5R, ±5%, SMD 0603; Manufacturer: Walsin Tech Corp; Manufacturer Part Number: 0603X105J100CT
footprint CAP-0603 (0603 (1608M) Capacitor)
pins: 1, 2

## 0603X105J160CT
designator C?  Capacitance: 1uF  (hidden comment: *)
Capacitor, Ceramic (MLCC), 1uF, ±5%, 16V, X5R, ±5%, SMD 0603; Manufacturer: Walsin Tech Corp; Manufacturer Part Number: 0603X105J160CT
footprint CAP-0603 (0603 (1608M) Capacitor)
pins: 1, 2

## 0603X105K6R3CT
designator C?  Capacitance: 1uF  (hidden comment: *)
Capacitor, Ceramic (MLCC), 1uF, ±10%, 6.3V, X5R, ±10%, SMD 0603; Manufacturer: Walsin Tech Corp; Manufacturer Part Number: 0603X105K6R3CT
footprint CAP-0603 (0603 (1608M) Capacitor)
pins: 1, 2

## 0603X105K100CT
designator C?  Capacitance: 1uF  (hidden comment: *)
Capacitor, Ceramic (MLCC), 1uF, ±10%, 10V, X5R, ±10%, SMD 0603; Manufacturer: Walsin Tech Corp; Manufacturer Part Number: 0603X105K100CT
footprint CAP-0603 (0603 (1608M) Capacitor)
pins: 1, 2

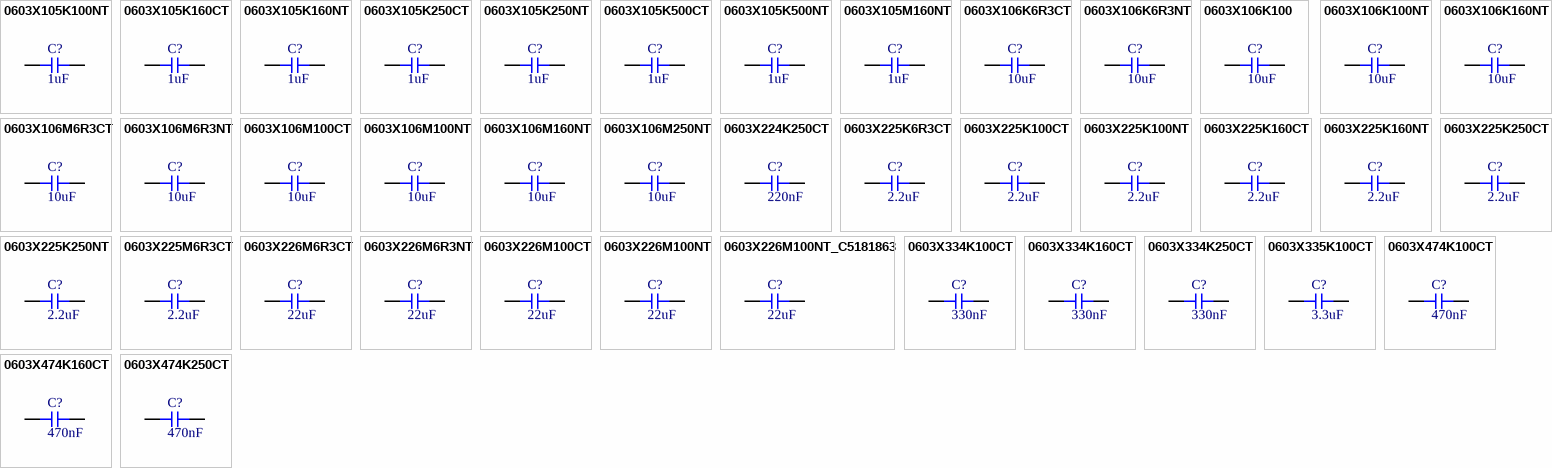
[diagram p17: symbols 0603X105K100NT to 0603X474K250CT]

## 0603X105K100NT
designator C?  Capacitance: 1uF  (hidden comment: *)
Capacitor, Ceramic (MLCC), 1uF, ±10%, 10V, X5R, ±10%, SMD 0603; Manufacturer: FH(Guangdong Fenghua Advanced Tech); Manufacturer Part Number: 0603X105K100NT
footprint CAP-0603 (0603 (1608M) Capacitor)
pins: 1, 2

## 0603X105K160CT
designator C?  Capacitance: 1uF  (hidden comment: *)
Capacitor, Ceramic (MLCC), 1uF, ±10%, 16V, X5R, ±10%, SMD 0603; Manufacturer: Walsin Tech Corp; Manufacturer Part Number: 0603X105K160CT
footprint CAP-0603 (0603 (1608M) Capacitor)
pins: 1, 2

## 0603X105K160NT
designator C?  Capacitance: 1uF  (hidden comment: *)
Capacitor, Ceramic (MLCC), 1uF, ±10%, 16V, X5R, ±10%, SMD 0603; Manufacturer: FH(Guangdong Fenghua Advanced Tech); Manufacturer Part Number: 0603X105K160NT
footprint CAP-0603 (0603 (1608M) Capacitor)
pins: 1, 2

## 0603X105K250CT
designator C?  Capacitance: 1uF  (hidden comment: *)
Capacitor, Ceramic (MLCC), 1uF, ±10%, 25V, X5R, ±10%, SMD 0603; Manufacturer: Walsin Tech Corp; Manufacturer Part Number: 0603X105K250CT
footprint CAP-0603 (0603 (1608M) Capacitor)
pins: 1, 2

## 0603X105K250NT
designator C?  Capacitance: 1uF  (hidden comment: *)
Capacitor, Ceramic (MLCC), 1uF, ±10%, 25V, X5R, ±10%, SMD 0603; Manufacturer: FH(Guangdong Fenghua Advanced Tech); Manufacturer Part Number: 0603X105K250NT
footprint CAP-0603 (0603 (1608M) Capacitor)
pins: 1, 2

## 0603X105K500CT
designator C?  Capacitance: 1uF  (hidden comment: *)
Capacitor, Ceramic (MLCC), 1uF, ±10%, 50V, X5R, ±10%, SMD 0603; Manufacturer: Walsin Tech Corp; Manufacturer Part Number: 0603X105K500CT
footprint CAP-0603 (0603 (1608M) Capacitor)
pins: 1, 2

## 0603X105K500NT
designator C?  Capacitance: 1uF  (hidden comment: *)
Capacitor, Ceramic (MLCC), 1uF, ±10%, 50V, X5R, ±10%, SMD 0603; Manufacturer: FH(Guangdong Fenghua Advanced Tech); Manufacturer Part Number: 0603X105K500NT
footprint CAP-0603 (0603 (1608M) Capacitor)
pins: 1, 2

## 0603X105M160NT
designator C?  Capacitance: 1uF  (hidden comment: *)
Capacitor, Ceramic (MLCC), 1uF, ±20%, 16V, X5R, ±20%, SMD 0603; Manufacturer: FH(Guangdong Fenghua Advanced Tech); Manufacturer Part Number: 0603X105M160NT
footprint CAP-0603 (0603 (1608M) Capacitor)
pins: 1, 2

## 0603X106K6R3CT
designator C?  Capacitance: 10uF  (hidden comment: *)
Capacitor, Ceramic (MLCC), 10uF, ±10%, 6.3V, X5R, ±10%, SMD 0603; Manufacturer: Walsin Tech Corp; Manufacturer Part Number: 0603X106K6R3CT
footprint CAP-0603 (0603 (1608M) Capacitor)
pins: 1, 2

## 0603X106K6R3NT
designator C?  Capacitance: 10uF  (hidden comment: *)
Capacitor, Ceramic (MLCC), 10uF, ±10%, 6.3V, X5R, ±10%, SMD 0603; Manufacturer: FH(Guangdong Fenghua Advanced Tech); Manufacturer Part Number: 0603X106K6R3NT
footprint CAP-0603 (0603 (1608M) Capacitor)
pins: 1, 2

## 0603X106K100
designator C?  Capacitance: 10uF  (hidden comment: *)
Capacitor, Ceramic (MLCC), 10uF, ±10%, 10V, X5R, ±10%, SMD 0603; Manufacturer: Walsin Tech Corp; Manufacturer Part Number: 0603X106K100
footprint CAP-0603 (0603 (1608M) Capacitor)
pins: 1, 2

## 0603X106K100NT
designator C?  Capacitance: 10uF  (hidden comment: *)
Capacitor, Ceramic (MLCC), 10uF, ±10%, 10V, X5R, ±10%, SMD 0603; Manufacturer: FH(Guangdong Fenghua Advanced Tech); Manufacturer Part Number: 0603X106K100NT
footprint CAP-0603 (0603 (1608M) Capacitor)
pins: 1, 2

## 0603X106K160NT
designator C?  Capacitance: 10uF  (hidden comment: *)
Capacitor, Ceramic (MLCC), 10uF, ±10%, 16V, X5R, ±10%, SMD 0603; Manufacturer: FH(Guangdong Fenghua Advanced Tech); Manufacturer Part Number: 0603X106K160NT
footprint CAP-0603 (0603 (1608M) Capacitor)
pins: 1, 2

## 0603X106M6R3CT
designator C?  Capacitance: 10uF  (hidden comment: *)
Capacitor, Ceramic (MLCC), 10uF, ±20%, 6.3V, X5R, ±20%, SMD 0603; Manufacturer: Walsin Tech Corp; Manufacturer Part Number: 0603X106M6R3CT
footprint CAP-0603 (0603 (1608M) Capacitor)
pins: 1, 2

## 0603X106M6R3NT
designator C?  Capacitance: 10uF  (hidden comment: *)
Capacitor, Ceramic (MLCC), 10uF, ±20%, 6.3V, X5R, ±20%, SMD 0603; Manufacturer: FH(Guangdong Fenghua Advanced Tech); Manufacturer Part Number: 0603X106M6R3NT
footprint CAP-0603 (0603 (1608M) Capacitor)
pins: 1, 2

## 0603X106M100CT
designator C?  Capacitance: 10uF  (hidden comment: *)
Capacitor, Ceramic (MLCC), 10uF, ±20%, 10V, X5R, ±20%, SMD 0603; Manufacturer: Walsin Tech Corp; Manufacturer Part Number: 0603X106M100CT
footprint CAP-0603 (0603 (1608M) Capacitor)
pins: 1, 2

## 0603X106M100NT
designator C?  Capacitance: 10uF  (hidden comment: *)
Capacitor, Ceramic (MLCC), 10uF, ±20%, 10V, X5R, ±20%, SMD 0603; Manufacturer: FH(Guangdong Fenghua Advanced Tech); Manufacturer Part Number: 0603X106M100NT
footprint CAP-0603 (0603 (1608M) Capacitor)
pins: 1, 2

## 0603X106M160NT
designator C?  Capacitance: 10uF  (hidden comment: *)
Capacitor, Ceramic (MLCC), 10uF, ±20%, 16V, X5R, ±20%, SMD 0603; Manufacturer: FH(Guangdong Fenghua Advanced Tech); Manufacturer Part Number: 0603X106M160NT
footprint CAP-0603 (0603 (1608M) Capacitor)
pins: 1, 2

## 0603X106M250NT
designator C?  Capacitance: 10uF  (hidden comment: *)
Capacitor, Ceramic (MLCC), 10uF, ±20%, 25V, X5R, ±20%, SMD 0603; Manufacturer: FH(Guangdong Fenghua Advanced Tech); Manufacturer Part Number: 0603X106M250NT
footprint CAP-0603 (0603 (1608M) Capacitor)
pins: 1, 2

## 0603X224K250CT
designator C?  Capacitance: 220nF  (hidden comment: *)
Capacitor, Ceramic (MLCC), 220nF, ±10%, 25V, X5R, ±10%, SMD 0603; Manufacturer: Walsin Tech Corp; Manufacturer Part Number: 0603X224K250CT
footprint CAP-0603 (0603 (1608M) Capacitor)
pins: 1, 2

## 0603X225K6R3CT
designator C?  Capacitance: 2.2uF  (hidden comment: *)
Capacitor, Ceramic (MLCC), 2.2uF, ±10%, 6.3V, X5R, ±10%, SMD 0603; Manufacturer: Walsin Tech Corp; Manufacturer Part Number: 0603X225K6R3CT
footprint CAP-0603 (0603 (1608M) Capacitor)
pins: 1, 2

## 0603X225K100CT
designator C?  Capacitance: 2.2uF  (hidden comment: *)
Capacitor, Ceramic (MLCC), 2.2uF, ±10%, 10V, X5R, ±10%, SMD 0603; Manufacturer: Walsin Tech Corp; Manufacturer Part Number: 0603X225K100CT
footprint CAP-0603 (0603 (1608M) Capacitor)
pins: 1, 2

## 0603X225K100NT
designator C?  Capacitance: 2.2uF  (hidden comment: *)
Capacitor, Ceramic (MLCC), 2.2uF, ±10%, 10V, X5R, ±10%, SMD 0603; Manufacturer: FH(Guangdong Fenghua Advanced Tech); Manufacturer Part Number: 0603X225K100NT
footprint CAP-0603 (0603 (1608M) Capacitor)
pins: 1, 2

## 0603X225K160CT
designator C?  Capacitance: 2.2uF  (hidden comment: *)
Capacitor, Ceramic (MLCC), 2.2uF, ±10%, 16V, X5R, ±10%, SMD 0603; Manufacturer: Walsin Tech Corp; Manufacturer Part Number: 0603X225K160CT
footprint CAP-0603 (0603 (1608M) Capacitor)
pins: 1, 2

## 0603X225K160NT
designator C?  Capacitance: 2.2uF  (hidden comment: *)
Capacitor, Ceramic (MLCC), 2.2uF, ±10%, 16V, X5R, ±10%, SMD 0603; Manufacturer: FH(Guangdong Fenghua Advanced Tech); Manufacturer Part Number: 0603X225K160NT
footprint CAP-0603 (0603 (1608M) Capacitor)
pins: 1, 2

## 0603X225K250CT
designator C?  Capacitance: 2.2uF  (hidden comment: *)
Capacitor, Ceramic (MLCC), 2.2uF, ±10%, 25V, X5R, ±10%, SMD 0603; Manufacturer: Walsin Tech Corp; Manufacturer Part Number: 0603X225K250CT
footprint CAP-0603 (0603 (1608M) Capacitor)
pins: 1, 2

## 0603X225K250NT
designator C?  Capacitance: 2.2uF  (hidden comment: *)
Capacitor, Ceramic (MLCC), 2.2uF, ±10%, 25V, X5R, ±10%, SMD 0603; Manufacturer: FH(Guangdong Fenghua Advanced Tech); Manufacturer Part Number: 0603X225K250NT
footprint CAP-0603 (0603 (1608M) Capacitor)
pins: 1, 2

## 0603X225M6R3CT
designator C?  Capacitance: 2.2uF  (hidden comment: *)
Capacitor, Ceramic (MLCC), 2.2uF, ±20%, 6.3V, X5R, ±20%, SMD 0603; Manufacturer: Walsin Tech Corp; Manufacturer Part Number: 0603X225M6R3CT
footprint CAP-0603 (0603 (1608M) Capacitor)
pins: 1, 2

## 0603X226M6R3CT
designator C?  Capacitance: 22uF  (hidden comment: *)
Capacitor, Ceramic (MLCC), 22uF, ±20%, 6.3V, X5R, ±20%, SMD 0603; Manufacturer: Walsin Tech Corp; Manufacturer Part Number: 0603X226M6R3CT
footprint CAP-0603 (0603 (1608M) Capacitor)
pins: 1, 2

## 0603X226M6R3NT
designator C?  Capacitance: 22uF  (hidden comment: *)
Capacitor, Ceramic (MLCC), 22uF, ±20%, 6.3V, X5R, ±20%, SMD 0603; Manufacturer: FH(Guangdong Fenghua Advanced Tech); Manufacturer Part Number: 0603X226M6R3NT
footprint CAP-0603 (0603 (1608M) Capacitor)
pins: 1, 2

## 0603X226M100CT
designator C?  Capacitance: 22uF  (hidden comment: *)
Capacitor, Ceramic (MLCC), 22uF, ±20%, 10V, X5R, ±20%, SMD 0603; Manufacturer: Walsin Tech Corp; Manufacturer Part Number: 0603X226M100CT
footprint CAP-0603 (0603 (1608M) Capacitor)
pins: 1, 2

## 0603X226M100NT
designator C?  Capacitance: 22uF  (hidden comment: *)
Capacitor, Ceramic (MLCC), 22uF, ±20%, 10V, X5R, ±20%, SMD 0603; Manufacturer: FH(Guangdong Fenghua Advanced Tech); Manufacturer Part Number: 0603X226M100NT
footprint CAP-0603 (0603 (1608M) Capacitor)
pins: 1, 2

## 0603X226M100NT_C5181863
designator C?  Capacitance: 22uF  (hidden comment: *)
Capacitor, Ceramic (MLCC), 22uF, ±20%, 10V, X5R, ±20%, SMD 0603; Manufacturer: FH (Guangdong Fenghua Advanced Tech); Manufacturer Part Number: 0603X226M100NT
footprint CAP-0603 (0603 (1608M) Capacitor)
pins: 1, 2

## 0603X334K100CT
designator C?  Capacitance: 330nF  (hidden comment: *)
Capacitor, Ceramic (MLCC), 330nF, ±10%, 10V, X5R, ±10%, SMD 0603; Manufacturer: Walsin Tech Corp; Manufacturer Part Number: 0603X334K100CT
footprint CAP-0603 (0603 (1608M) Capacitor)
pins: 1, 2

## 0603X334K160CT
designator C?  Capacitance: 330nF  (hidden comment: *)
Capacitor, Ceramic (MLCC), 330nF, ±10%, 16V, X5R, ±10%, SMD 0603; Manufacturer: Walsin Tech Corp; Manufacturer Part Number: 0603X334K160CT
footprint CAP-0603 (0603 (1608M) Capacitor)
pins: 1, 2

## 0603X334K250CT
designator C?  Capacitance: 330nF  (hidden comment: *)
Capacitor, Ceramic (MLCC), 330nF, ±10%, 25V, X5R, ±10%, SMD 0603; Manufacturer: Walsin Tech Corp; Manufacturer Part Number: 0603X334K250CT
footprint CAP-0603 (0603 (1608M) Capacitor)
pins: 1, 2

## 0603X335K100CT
designator C?  Capacitance: 3.3uF  (hidden comment: *)
Capacitor, Ceramic (MLCC), 3.3uF, ±10%, 10V, X5R, ±10%, SMD 0603; Manufacturer: Walsin Tech Corp; Manufacturer Part Number: 0603X335K100CT
footprint CAP-0603 (0603 (1608M) Capacitor)
pins: 1, 2

## 0603X474K100CT
designator C?  Capacitance: 470nF  (hidden comment: *)
Capacitor, Ceramic (MLCC), 470nF, ±10%, 10V, X5R, ±10%, SMD 0603; Manufacturer: Walsin Tech Corp; Manufacturer Part Number: 0603X474K100CT
footprint CAP-0603 (0603 (1608M) Capacitor)
pins: 1, 2

## 0603X474K160CT
designator C?  Capacitance: 470nF  (hidden comment: *)
Capacitor, Ceramic (MLCC), 470nF, ±10%, 16V, X5R, ±10%, SMD 0603; Manufacturer: Walsin Tech Corp; Manufacturer Part Number: 0603X474K160CT
footprint CAP-0603 (0603 (1608M) Capacitor)
pins: 1, 2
